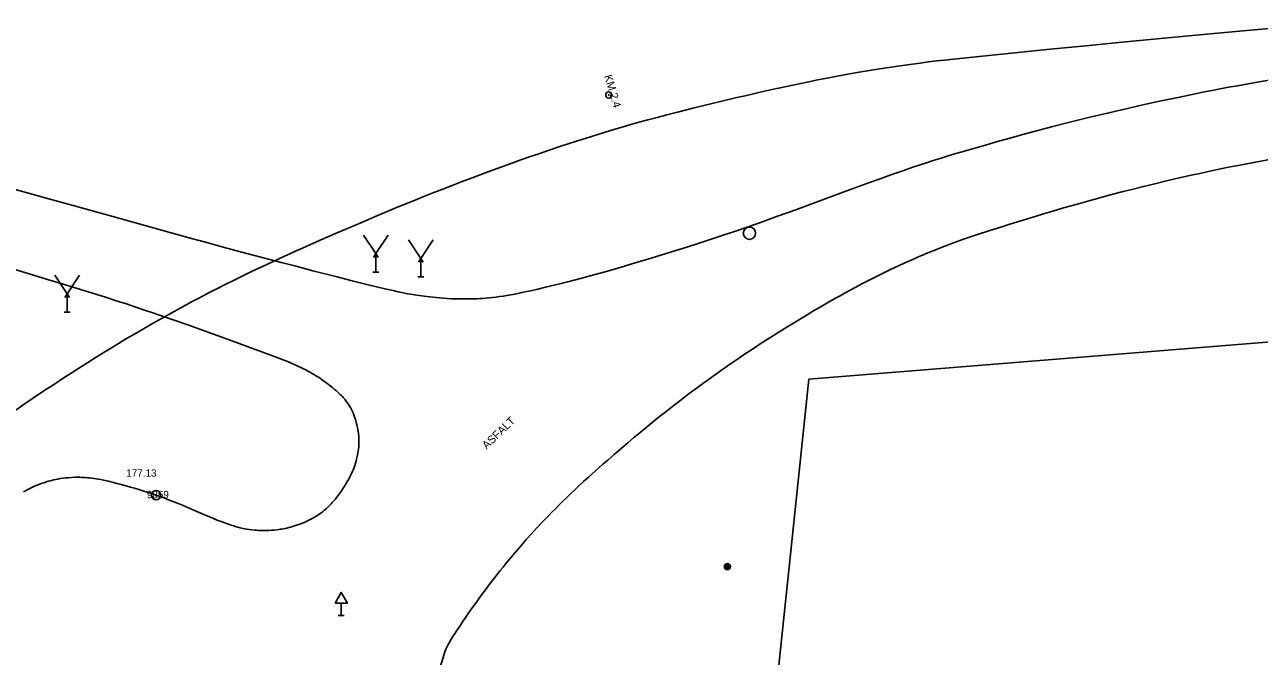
# Model space of a CAD drawing. Extents: x -541281 to -539153, y -1183881 to -1182141.
# Drawn here: x -539780.8 to -539680.5, y -1183225.4 to -1183174.1 of the extents above; entities that cross this region are included whole.
import ezdxf

# ---------------------------------------------------------------- set-up
doc = ezdxf.new("R2010")
doc.units = 0
for name, color, linetype in [('Vrstva 10', 7, 'Continuous'), ('Vrstva 12', 7, 'Continuous'), ('Vrstva 13', 7, 'Continuous'), ('Vrstva 21', 7, 'Continuous'), ('Vrstva 22', 7, 'Continuous'), ('Vrstva 23', 7, 'Continuous'), ('Vrstva 25', 7, 'Continuous'), ('Vrstva 27', 7, 'Continuous'), ('Vrstva 34', 7, 'Continuous'), ('Vrstva 40', 7, 'Continuous'), ('Vrstva 7', 7, 'Continuous')]:
    doc.layers.add(name, color=color, linetype=linetype)

msp = doc.modelspace()

# ---------------------------------------------------------------- linework, layer by layer
at = {"layer": 'Vrstva 10'}
for p, q in [((-539683.71, -1183179.3), (-539684.37, -1183179.43)), ((-539693.72, -1183181.46), (-539694.41, -1183181.63)), ((-539703.64, -1183184.1), (-539704.68, -1183184.4)), ((-539687.05, -1183186.53), (-539688.08, -1183186.77)), ((-539763.31, -1183192.52), (-539764.72, -1183192.14)), ((-539710.49, -1183193.97), (-539711.14, -1183194.28)), ((-539734.6, -1183194.4), (-539735.4, -1183194.61)), ((-539776.04, -1183195.67), (-539774.28, -1183196.22)), ((-539727.86, -1183204.82), (-539728.32, -1183205.17)), ((-539735.81, -1183211.53), (-539736.16, -1183211.86))]:
    msp.add_line(p, q, dxfattribs=at)
for points in [[(-539673.85, -1183177.7), (-539674.82, -1183177.83), (-539675.77, -1183177.97), (-539676.68, -1183178.1), (-539677.57, -1183178.24), (-539678.43, -1183178.38), (-539679.26, -1183178.51), (-539680.06, -1183178.65), (-539680.84, -1183178.78), (-539681.59, -1183178.91), (-539682.32, -1183179.04), (-539683.03, -1183179.17), (-539683.71, -1183179.3)], [(-539684.37, -1183179.43), (-539685.01, -1183179.55), (-539686.25, -1183179.8), (-539687.41, -1183180.04), (-539688.5, -1183180.27), (-539689.52, -1183180.49), (-539690.47, -1183180.7), (-539691.37, -1183180.91), (-539692.2, -1183181.1), (-539692.99, -1183181.29), (-539693.72, -1183181.46)], [(-539694.41, -1183181.63), (-539695.06, -1183181.79), (-539696.26, -1183182.09), (-539697.32, -1183182.36), (-539698.24, -1183182.6), (-539699.05, -1183182.82), (-539699.76, -1183183.01), (-539700.99, -1183183.35), (-539701.91, -1183183.6), (-539702.6, -1183183.8), (-539703.64, -1183184.1)], [(-539704.68, -1183184.4), (-539705.3, -1183184.58), (-539705.9, -1183184.77), (-539706.47, -1183184.95), (-539707.03, -1183185.12), (-539707.57, -1183185.3), (-539708.09, -1183185.47), (-539708.6, -1183185.64), (-539709.57, -1183185.97), (-539710.48, -1183186.29), (-539711.33, -1183186.59), (-539712.13, -1183186.88), (-539713.63, -1183187.42)], [(-539677.76, -1183184.69), (-539678.57, -1183184.83), (-539679.35, -1183184.96), (-539680.11, -1183185.1), (-539680.85, -1183185.24), (-539681.56, -1183185.37), (-539682.25, -1183185.51), (-539682.92, -1183185.64), (-539683.57, -1183185.77), (-539684.19, -1183185.9), (-539684.8, -1183186.03), (-539685.38, -1183186.16), (-539685.95, -1183186.28), (-539687.05, -1183186.53)], [(-539773.67, -1183189.67), (-539776.71, -1183188.82), (-539779, -1183188.19), (-539780.71, -1183187.72), (-539782, -1183187.37), (-539782.97, -1183187.11)], [(-539688.08, -1183186.77), (-539689.04, -1183187), (-539689.95, -1183187.22), (-539690.79, -1183187.44), (-539691.59, -1183187.64), (-539692.33, -1183187.83)], [(-539713.63, -1183187.42), (-539716.24, -1183188.39), (-539718.19, -1183189.11), (-539719.67, -1183189.64), (-539720.77, -1183190.04), (-539721.6, -1183190.33), (-539722.23, -1183190.55)], [(-539692.33, -1183187.83), (-539693.03, -1183188.02), (-539693.68, -1183188.19), (-539694.29, -1183188.36), (-539695.43, -1183188.68), (-539696.44, -1183188.97), (-539697.31, -1183189.22), (-539698.08, -1183189.45), (-539698.75, -1183189.65), (-539699.92, -1183190.01), (-539700.8, -1183190.28), (-539701.46, -1183190.49)], [(-539764.72, -1183192.14), (-539766.05, -1183191.78), (-539767.28, -1183191.44), (-539769.61, -1183190.8), (-539773.67, -1183189.67)], [(-539722.23, -1183190.55), (-539723.17, -1183190.87), (-539724.11, -1183191.18), (-539725.16, -1183191.52)], [(-539701.46, -1183190.49), (-539702.44, -1183190.8), (-539703.43, -1183191.12), (-539704, -1183191.31), (-539704.56, -1183191.5), (-539705.09, -1183191.69), (-539705.6, -1183191.88), (-539706.09, -1183192.07), (-539706.57, -1183192.25), (-539707.03, -1183192.44), (-539707.47, -1183192.62), (-539707.89, -1183192.8), (-539708.31, -1183192.97), (-539708.7, -1183193.15), (-539709.09, -1183193.32), (-539709.46, -1183193.49), (-539709.81, -1183193.65), (-539710.16, -1183193.81), (-539710.49, -1183193.97)], [(-539725.16, -1183191.52), (-539726.14, -1183191.84), (-539727.06, -1183192.14), (-539727.93, -1183192.41), (-539728.74, -1183192.67), (-539729.5, -1183192.9), (-539730.21, -1183193.12), (-539730.88, -1183193.32), (-539731.51, -1183193.51), (-539732.1, -1183193.69), (-539732.66, -1183193.85), (-539733.69, -1183194.15), (-539734.6, -1183194.4)], [(-539785.21, -1183192.9), (-539783.84, -1183193.3), (-539782.64, -1183193.66), (-539780.55, -1183194.29), (-539778.98, -1183194.77), (-539777.8, -1183195.13), (-539776.04, -1183195.67)], [(-539754.34, -1183194.85), (-539755.46, -1183194.56), (-539757.43, -1183194.06), (-539758.9, -1183193.68), (-539760, -1183193.4), (-539761.66, -1183192.96), (-539763.31, -1183192.52)], [(-539745.01, -1183196.36), (-539745.43, -1183196.36), (-539745.82, -1183196.35), (-539746.18, -1183196.34), (-539746.52, -1183196.32), (-539746.84, -1183196.3), (-539747.14, -1183196.27), (-539747.42, -1183196.25), (-539747.69, -1183196.22), (-539747.93, -1183196.19), (-539748.4, -1183196.14), (-539748.8, -1183196.08), (-539749.15, -1183196.03), (-539749.46, -1183195.97), (-539749.73, -1183195.93), (-539750.19, -1183195.84), (-539750.54, -1183195.77), (-539750.8, -1183195.71), (-539751.19, -1183195.62), (-539751.58, -1183195.53), (-539753.05, -1183195.17), (-539754.34, -1183194.85)], [(-539735.4, -1183194.61), (-539736.1, -1183194.8), (-539736.71, -1183194.96), (-539737.25, -1183195.09), (-539737.72, -1183195.21), (-539738.54, -1183195.41), (-539739.16, -1183195.55), (-539739.62, -1183195.66), (-539740.32, -1183195.81), (-539741.02, -1183195.96), (-539741.34, -1183196.02), (-539741.66, -1183196.08), (-539741.96, -1183196.13), (-539742.26, -1183196.17), (-539742.55, -1183196.21), (-539742.83, -1183196.24), (-539743.1, -1183196.27), (-539743.37, -1183196.29), (-539743.62, -1183196.31), (-539743.87, -1183196.33), (-539744.11, -1183196.34), (-539744.35, -1183196.35), (-539744.58, -1183196.36), (-539744.8, -1183196.36), (-539745.01, -1183196.36)], [(-539711.14, -1183194.28), (-539711.74, -1183194.58), (-539712.3, -1183194.86), (-539712.82, -1183195.14), (-539713.31, -1183195.39), (-539713.77, -1183195.64), (-539714.19, -1183195.87), (-539714.59, -1183196.09), (-539714.97, -1183196.3), (-539715.67, -1183196.7), (-539716.28, -1183197.05), (-539716.81, -1183197.36), (-539717.27, -1183197.64), (-539717.68, -1183197.88), (-539718.39, -1183198.31), (-539718.92, -1183198.64), (-539719.71, -1183199.14)], [(-539774.28, -1183196.22), (-539773.4, -1183196.5), (-539772.58, -1183196.76), (-539771.82, -1183197.02), (-539771.1, -1183197.26), (-539770.43, -1183197.48), (-539769.8, -1183197.7), (-539768.62, -1183198.11), (-539767.59, -1183198.47), (-539766.69, -1183198.79), (-539765.12, -1183199.36)], [(-539719.71, -1183199.14), (-539720.51, -1183199.64), (-539721, -1183199.95), (-539721.47, -1183200.26), (-539721.93, -1183200.56), (-539722.36, -1183200.85), (-539722.78, -1183201.14), (-539723.19, -1183201.41), (-539723.58, -1183201.68), (-539723.96, -1183201.94), (-539724.32, -1183202.2), (-539725.02, -1183202.7), (-539725.67, -1183203.17), (-539726.28, -1183203.62), (-539726.85, -1183204.04), (-539727.37, -1183204.44), (-539727.86, -1183204.82)], [(-539765.12, -1183199.36), (-539763.94, -1183199.79), (-539762.17, -1183200.44), (-539760.4, -1183201.09), (-539760.05, -1183201.22), (-539759.72, -1183201.35), (-539759.42, -1183201.47), (-539759.14, -1183201.59), (-539758.88, -1183201.7), (-539758.64, -1183201.81), (-539758.41, -1183201.92), (-539758.2, -1183202.02), (-539758.01, -1183202.12), (-539757.83, -1183202.22), (-539757.66, -1183202.31), (-539757.5, -1183202.4), (-539757.35, -1183202.49), (-539757.21, -1183202.57), (-539757.08, -1183202.65), (-539756.84, -1183202.8), (-539756.64, -1183202.95), (-539756.45, -1183203.08), (-539756.29, -1183203.19), (-539756.15, -1183203.3), (-539756.03, -1183203.4)], [(-539756.03, -1183203.4), (-539755.82, -1183203.57), (-539755.66, -1183203.7), (-539755.54, -1183203.8), (-539755.37, -1183203.96), (-539755.19, -1183204.13), (-539755.11, -1183204.21)], [(-539755.11, -1183204.21), (-539755.03, -1183204.29), (-539754.96, -1183204.37), (-539754.89, -1183204.45), (-539754.82, -1183204.52), (-539754.77, -1183204.6), (-539754.66, -1183204.74), (-539754.56, -1183204.88), (-539754.47, -1183205.02), (-539754.4, -1183205.14), (-539754.33, -1183205.26), (-539754.28, -1183205.37), (-539754.22, -1183205.48), (-539754.18, -1183205.58), (-539754.14, -1183205.68), (-539754.07, -1183205.85), (-539754.01, -1183206.01), (-539753.97, -1183206.15), (-539753.93, -1183206.27)], [(-539728.32, -1183205.17), (-539728.75, -1183205.51), (-539729.15, -1183205.83), (-539729.53, -1183206.13), (-539730.23, -1183206.69), (-539730.84, -1183207.19), (-539731.37, -1183207.64), (-539731.83, -1183208.03), (-539732.23, -1183208.37), (-539732.94, -1183208.98), (-539733.47, -1183209.44), (-539733.86, -1183209.78), (-539734.46, -1183210.31), (-539735.05, -1183210.84), (-539735.44, -1183211.19), (-539735.81, -1183211.53)], [(-539753.93, -1183206.27), (-539753.9, -1183206.38), (-539753.85, -1183206.57), (-539753.82, -1183206.71), (-539753.78, -1183206.92), (-539753.75, -1183207.13), (-539753.73, -1183207.25), (-539753.72, -1183207.37), (-539753.71, -1183207.48), (-539753.7, -1183207.59), (-539753.7, -1183207.7), (-539753.69, -1183207.81), (-539753.69, -1183208.01), (-539753.7, -1183208.2), (-539753.71, -1183208.39), (-539753.73, -1183208.56), (-539753.75, -1183208.72), (-539753.77, -1183208.87), (-539753.8, -1183209.01), (-539753.82, -1183209.14), (-539753.85, -1183209.27), (-539753.88, -1183209.38), (-539753.91, -1183209.49), (-539753.96, -1183209.7), (-539754.02, -1183209.87), (-539754.08, -1183210.03), (-539754.13, -1183210.17), (-539754.18, -1183210.28), (-539754.27, -1183210.49), (-539754.34, -1183210.64), (-539754.4, -1183210.76), (-539754.48, -1183210.93), (-539754.58, -1183211.1), (-539754.66, -1183211.24), (-539754.74, -1183211.37), (-539754.81, -1183211.49), (-539754.96, -1183211.73), (-539755.11, -1183211.94), (-539755.24, -1183212.14), (-539755.38, -1183212.31), (-539755.5, -1183212.48), (-539755.62, -1183212.63), (-539755.74, -1183212.76), (-539755.85, -1183212.89), (-539755.95, -1183213), (-539756.05, -1183213.1), (-539756.15, -1183213.2), (-539756.24, -1183213.29), (-539756.33, -1183213.37), (-539756.5, -1183213.51), (-539756.65, -1183213.64), (-539756.79, -1183213.74), (-539756.91, -1183213.83), (-539757.02, -1183213.91), (-539757.12, -1183213.97), (-539757.3, -1183214.08), (-539757.43, -1183214.16), (-539757.54, -1183214.22), (-539757.7, -1183214.3), (-539757.86, -1183214.38), (-539758.05, -1183214.47)], [(-539775.73, -1183210.88), (-539775.9, -1183210.86), (-539776.06, -1183210.85), (-539776.21, -1183210.85), (-539776.36, -1183210.84), (-539776.5, -1183210.84), (-539776.65, -1183210.84), (-539776.78, -1183210.84), (-539777.05, -1183210.85), (-539777.3, -1183210.87), (-539777.53, -1183210.89), (-539777.75, -1183210.92), (-539777.95, -1183210.95), (-539778.14, -1183210.98), (-539778.32, -1183211.02), (-539778.49, -1183211.05), (-539778.65, -1183211.09), (-539778.79, -1183211.13), (-539778.93, -1183211.16), (-539779.06, -1183211.2), (-539779.3, -1183211.28), (-539779.51, -1183211.35), (-539779.69, -1183211.42), (-539779.85, -1183211.48), (-539779.99, -1183211.54), (-539780.11, -1183211.59), (-539780.32, -1183211.69), (-539780.47, -1183211.77), (-539780.59, -1183211.83), (-539780.77, -1183211.93), (-539780.94, -1183212.03)], [(-539766.29, -1183213.86), (-539767.25, -1183213.45), (-539767.97, -1183213.14), (-539768.52, -1183212.92), (-539768.93, -1183212.75), (-539769.23, -1183212.63), (-539769.47, -1183212.54), (-539769.82, -1183212.41), (-539770.17, -1183212.29), (-539770.7, -1183212.11), (-539771.17, -1183211.96), (-539771.58, -1183211.83), (-539771.93, -1183211.73), (-539772.25, -1183211.63), (-539772.52, -1183211.55), (-539773, -1183211.42), (-539773.37, -1183211.33), (-539773.64, -1183211.26), (-539774.04, -1183211.16), (-539774.45, -1183211.07), (-539774.65, -1183211.03), (-539774.84, -1183210.99), (-539775.03, -1183210.96), (-539775.21, -1183210.94), (-539775.39, -1183210.91), (-539775.57, -1183210.89), (-539775.73, -1183210.88)], [(-539736.16, -1183211.86), (-539736.5, -1183212.19), (-539736.83, -1183212.5), (-539737.14, -1183212.8), (-539737.44, -1183213.1), (-539737.73, -1183213.39), (-539738.01, -1183213.67), (-539738.27, -1183213.94), (-539738.53, -1183214.2), (-539738.78, -1183214.46), (-539739.25, -1183214.97), (-539739.68, -1183215.44), (-539740.09, -1183215.89), (-539740.46, -1183216.32), (-539740.81, -1183216.72), (-539741.14, -1183217.1), (-539741.44, -1183217.46), (-539741.72, -1183217.8), (-539741.98, -1183218.13), (-539742.23, -1183218.43), (-539742.46, -1183218.72), (-539742.67, -1183218.99)], [(-539758.05, -1183214.47), (-539758.23, -1183214.54), (-539758.41, -1183214.61), (-539758.58, -1183214.68), (-539758.75, -1183214.74), (-539758.92, -1183214.79), (-539759.08, -1183214.84), (-539759.24, -1183214.88), (-539759.39, -1183214.92), (-539759.54, -1183214.96), (-539759.68, -1183214.99), (-539759.82, -1183215.02), (-539759.95, -1183215.04), (-539760.08, -1183215.06), (-539760.34, -1183215.1), (-539760.58, -1183215.12), (-539760.8, -1183215.14), (-539761.01, -1183215.15), (-539761.21, -1183215.16), (-539761.39, -1183215.16), (-539761.56, -1183215.16), (-539761.72, -1183215.16), (-539761.88, -1183215.15), (-539762.02, -1183215.14), (-539762.15, -1183215.13), (-539762.39, -1183215.1), (-539762.61, -1183215.08), (-539762.79, -1183215.05), (-539762.96, -1183215.02), (-539763.1, -1183214.99), (-539763.34, -1183214.94), (-539763.52, -1183214.89), (-539763.66, -1183214.85), (-539763.86, -1183214.79), (-539764.06, -1183214.73), (-539764.44, -1183214.6), (-539764.8, -1183214.46), (-539765.14, -1183214.34), (-539765.45, -1183214.21), (-539765.74, -1183214.09), (-539766.29, -1183213.86)], [(-539742.67, -1183218.99), (-539743.07, -1183219.51), (-539743.41, -1183219.97), (-539743.71, -1183220.37), (-539743.98, -1183220.73), (-539744.2, -1183221.05), (-539744.4, -1183221.33), (-539744.75, -1183221.83), (-539745.01, -1183222.2), (-539745.21, -1183222.49), (-539745.5, -1183222.92), (-539745.79, -1183223.36), (-539745.88, -1183223.5), (-539746.06, -1183223.78), (-539746.21, -1183224.04), (-539746.35, -1183224.29), (-539746.48, -1183224.52), (-539746.59, -1183224.74), (-539746.69, -1183224.94), (-539747.18, -1183226.52)]]:
    msp.add_lwpolyline(points, dxfattribs=at)
at = {"layer": 'Vrstva 12'}
for p, q in [((-539752.32, -1183194.17), (-539752.32, -1183192.67)), ((-539748.66, -1183194.56), (-539748.66, -1183193.06)), ((-539752.57, -1183194.17), (-539752.07, -1183194.17)), ((-539748.91, -1183194.56), (-539748.41, -1183194.56)), ((-539777.39, -1183197.43), (-539777.39, -1183195.93)), ((-539777.64, -1183197.43), (-539777.14, -1183197.43))]:
    msp.add_line(p, q, dxfattribs=at)
for points in [[(-539753.32, -1183191.17), (-539752.32, -1183192.67), (-539751.32, -1183191.17)], [(-539749.66, -1183191.56), (-539748.66, -1183193.06), (-539747.66, -1183191.56)], [(-539752.51, -1183192.98), (-539752.32, -1183192.67), (-539752.13, -1183192.98)], [(-539748.85, -1183193.36), (-539748.66, -1183193.06), (-539748.47, -1183193.36)], [(-539778.39, -1183194.43), (-539777.39, -1183195.93), (-539776.39, -1183194.43)], [(-539777.58, -1183196.24), (-539777.39, -1183195.93), (-539777.2, -1183196.24)]]:
    msp.add_lwpolyline(points, dxfattribs=at)
at = {"layer": 'Vrstva 13'}
for p, q in [((-539684.52, -1183174.83), (-539687.13, -1183175.07)), ((-539694.91, -1183175.82), (-539697.53, -1183176.08)), ((-539730.23, -1183181.82), (-539730.94, -1183182.01)), ((-539750.63, -1183188.94), (-539751.59, -1183189.34)), ((-539778.35, -1183203.22), (-539778.98, -1183203.63))]:
    msp.add_line(p, q, dxfattribs=at)
for points in [[(-539676.31, -1183174.08), (-539678.13, -1183174.25), (-539681.54, -1183174.55), (-539684.52, -1183174.83)], [(-539687.13, -1183175.07), (-539689.41, -1183175.29), (-539691.41, -1183175.48), (-539694.91, -1183175.82)], [(-539697.53, -1183176.08), (-539701.46, -1183176.48), (-539705.39, -1183176.88), (-539706.1, -1183176.96), (-539706.79, -1183177.03), (-539707.45, -1183177.11)], [(-539707.45, -1183177.11), (-539708.09, -1183177.2), (-539708.71, -1183177.28), (-539709.32, -1183177.36), (-539709.9, -1183177.45), (-539710.46, -1183177.53), (-539711.01, -1183177.61)], [(-539711.01, -1183177.61), (-539711.54, -1183177.7), (-539712.05, -1183177.78), (-539713.04, -1183177.95), (-539713.97, -1183178.11), (-539714.84, -1183178.27), (-539715.65, -1183178.43), (-539716.42, -1183178.57), (-539717.13, -1183178.72), (-539717.8, -1183178.85), (-539718.43, -1183178.99), (-539719.6, -1183179.24), (-539720.63, -1183179.46)], [(-539720.63, -1183179.46), (-539721.53, -1183179.67), (-539722.31, -1183179.85), (-539723, -1183180.01), (-539724.2, -1183180.29), (-539725.1, -1183180.51), (-539726.45, -1183180.84), (-539727.8, -1183181.18), (-539728.67, -1183181.4), (-539729.47, -1183181.61), (-539730.23, -1183181.82)], [(-539730.94, -1183182.01), (-539731.6, -1183182.2), (-539732.22, -1183182.38)], [(-539732.22, -1183182.38), (-539732.8, -1183182.55), (-539733.34, -1183182.71), (-539734.35, -1183183.02), (-539735.24, -1183183.29), (-539736.01, -1183183.54), (-539736.69, -1183183.76), (-539737.28, -1183183.95), (-539738.31, -1183184.29), (-539739.08, -1183184.56), (-539739.66, -1183184.76), (-539740.53, -1183185.06), (-539741.4, -1183185.37)], [(-539741.4, -1183185.37), (-539742.47, -1183185.76), (-539743.48, -1183186.13), (-539744.41, -1183186.48), (-539745.29, -1183186.81), (-539746.11, -1183187.13), (-539746.88, -1183187.43), (-539747.6, -1183187.72), (-539748.27, -1183187.98), (-539749.53, -1183188.49), (-539750.63, -1183188.94)], [(-539751.59, -1183189.34), (-539752.43, -1183189.69), (-539753.16, -1183190), (-539754.44, -1183190.55), (-539755.4, -1183190.96), (-539756.84, -1183191.59), (-539758.28, -1183192.22), (-539758.8, -1183192.45), (-539759.3, -1183192.68), (-539759.79, -1183192.9), (-539760.72, -1183193.33)], [(-539760.72, -1183193.33), (-539761.59, -1183193.74), (-539762.41, -1183194.13), (-539763.17, -1183194.5), (-539763.88, -1183194.85), (-539764.55, -1183195.18), (-539765.17, -1183195.5), (-539765.75, -1183195.79), (-539766.3, -1183196.08), (-539766.8, -1183196.35), (-539767.28, -1183196.6), (-539768.17, -1183197.08), (-539768.95, -1183197.5)], [(-539770.21, -1183198.22), (-539770.73, -1183198.51), (-539771.18, -1183198.77), (-539771.97, -1183199.23), (-539772.56, -1183199.58), (-539773, -1183199.84), (-539773.66, -1183200.25), (-539774.32, -1183200.65), (-539775.03, -1183201.09), (-539775.72, -1183201.52), (-539776.4, -1183201.95), (-539777.06, -1183202.38), (-539777.71, -1183202.8), (-539778.35, -1183203.22)], [(-539768.95, -1183197.5), (-539769.62, -1183197.88), (-539770.21, -1183198.22)], [(-539778.98, -1183203.63), (-539779.6, -1183204.04), (-539780.2, -1183204.45), (-539780.8, -1183204.85), (-539781.38, -1183205.25), (-539781.95, -1183205.64), (-539782.51, -1183206.03), (-539783.06, -1183206.41), (-539783.6, -1183206.79), (-539784.13, -1183207.17), (-539784.65, -1183207.54), (-539785.16, -1183207.91), (-539786.17, -1183208.64), (-539787.13, -1183209.35)]]:
    msp.add_lwpolyline(points, dxfattribs=at)
at = {"layer": 'Vrstva 21'}
for radius in [0.375, 0.05]:
    msp.add_circle((-539770.17, -1183212.29), radius, dxfattribs=at)
at = {"layer": 'Vrstva 25'}
for centre, radius in [((-539733.39, -1183179.79), 0.25), ((-539733.39, -1183179.79), 0.0303), ((-539723.75, -1183218.09), 0.25), ((-539723.75, -1183218.09), 0.2), ((-539723.75, -1183218.09), 0.15), ((-539723.75, -1183218.09), 0.1), ((-539723.75, -1183218.09), 0.05)]:
    msp.add_circle(centre, radius, dxfattribs=at)
at = {"layer": 'Vrstva 27'}
msp.add_circle((-539721.96, -1183191.02), 0.5, dxfattribs=at)
at = {"layer": 'Vrstva 34'}
for p, q in [((-539755.13, -1183221.05), (-539755.13, -1183222.07)), ((-539755.38, -1183222.07), (-539754.88, -1183222.07))]:
    msp.add_line(p, q, dxfattribs=at)
msp.add_lwpolyline([(-539755.63, -1183221.05), (-539754.63, -1183221.05), (-539755.13, -1183220.19)], close=True, dxfattribs=at)
at = {"layer": 'Vrstva 7'}
msp.add_line((-539717.15, -1183202.86), (-539603.45, -1183193.7), dxfattribs=at)
msp.add_lwpolyline([(-539735.64, -1183375.86), (-539735, -1183369.96), (-539726.24, -1183289.32), (-539718.71, -1183217.87), (-539717.15, -1183202.86)], dxfattribs=at)

# ---------------------------------------------------------------- texts
at = {"layer": 'Vrstva 22'}
msp.add_text('177.13', height=0.6, dxfattribs=at).set_placement((-539772.59, -1183210.79))
at = {"layer": 'Vrstva 23'}
msp.add_text('9859', height=0.6, dxfattribs=at).set_placement((-539770.92, -1183212.54))
at = {"layer": 'Vrstva 40'}
for s, rotation, p in [('KM 2.4', 286.4186, (-539733.77, -1183178.25)), ('ASFALT', 43.8093, (-539743.31, -1183208.6))]:
    msp.add_text(s, height=0.65, rotation=rotation, dxfattribs=at).set_placement(p)

doc.saveas('drawing.dxf')
